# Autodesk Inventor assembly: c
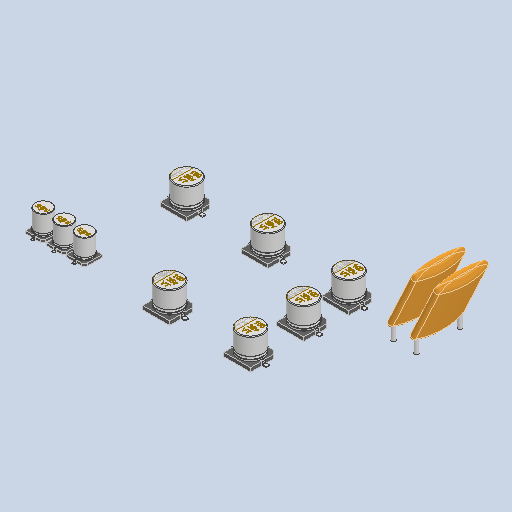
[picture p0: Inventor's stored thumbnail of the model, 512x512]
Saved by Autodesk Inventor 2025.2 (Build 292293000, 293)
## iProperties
Created: 2025-04
Part Number: c
Description: PART--DESC
Document SubType Name: Assembly
Designer: BennF
Author: BennF
Revision Number: NONE
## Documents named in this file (12)
- C:\Users\BennF\Nextcloud\Benutzer\CNC JarBeRi\existing parts\Electronics\RepRap A4988 Shied (USE WITHOUT ARDUINO)\reprap-a4988-1.snapshot.1\RepRap\RepRap\c.iam
- C:\Users\BennF\Nextcloud\Benutzer\CNC JarBeRi\existing parts\Electronics\RepRap A4988 Shied (USE WITHOUT ARDUINO)\reprap-a4988-1.snapshot.1\RepRap\RepRap\C100.iam
- C:\Users\BennF\Nextcloud\Benutzer\CNC JarBeRi\existing parts\Electronics\RepRap A4988 Shied (USE WITHOUT ARDUINO)\reprap-a4988-1.snapshot.1\RepRap\RepRap\C100_1.iam
- C:\Users\BennF\Nextcloud\Benutzer\CNC JarBeRi\existing parts\Electronics\RepRap A4988 Shied (USE WITHOUT ARDUINO)\reprap-a4988-1.snapshot.1\RepRap\RepRap\C100_2.iam
- C:\Users\BennF\Nextcloud\Benutzer\CNC JarBeRi\existing parts\Electronics\RepRap A4988 Shied (USE WITHOUT ARDUINO)\reprap-a4988-1.snapshot.1\RepRap\RepRap\C100_3.iam
- C:\Users\BennF\Nextcloud\Benutzer\CNC JarBeRi\existing parts\Electronics\RepRap A4988 Shied (USE WITHOUT ARDUINO)\reprap-a4988-1.snapshot.1\RepRap\RepRap\C100_4.iam
- C:\Users\BennF\Nextcloud\Benutzer\CNC JarBeRi\existing parts\Electronics\RepRap A4988 Shied (USE WITHOUT ARDUINO)\reprap-a4988-1.snapshot.1\RepRap\RepRap\C100_5.iam
- C:\Users\BennF\Nextcloud\Benutzer\CNC JarBeRi\existing parts\Electronics\RepRap A4988 Shied (USE WITHOUT ARDUINO)\reprap-a4988-1.snapshot.1\RepRap\RepRap\C10.iam
- C:\Users\BennF\Nextcloud\Benutzer\CNC JarBeRi\existing parts\Electronics\RepRap A4988 Shied (USE WITHOUT ARDUINO)\reprap-a4988-1.snapshot.1\RepRap\RepRap\C10_1.iam
- C:\Users\BennF\Nextcloud\Benutzer\CNC JarBeRi\existing parts\Electronics\RepRap A4988 Shied (USE WITHOUT ARDUINO)\reprap-a4988-1.snapshot.1\RepRap\RepRap\C10_2.iam
- C:\Users\BennF\Nextcloud\Benutzer\CNC JarBeRi\existing parts\Electronics\RepRap A4988 Shied (USE WITHOUT ARDUINO)\reprap-a4988-1.snapshot.1\RepRap\RepRap\Cp.iam
- C:\Users\BennF\Nextcloud\Benutzer\CNC JarBeRi\existing parts\Electronics\RepRap A4988 Shied (USE WITHOUT ARDUINO)\reprap-a4988-1.snapshot.1\RepRap\RepRap\Cp_1.iam
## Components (11 placed, 3 different names)
1. C100 [sub-assembly]
2. C100:1 [sub-assembly]
3. C100:2 [sub-assembly]
4. C100:3 [sub-assembly]
5. C100:4 [sub-assembly]
6. C100:5 [sub-assembly]
7. C10 [sub-assembly]
8. C10:1 [sub-assembly]
9. C10:2 [sub-assembly]
10. Cp [sub-assembly]
11. Cp:1 [sub-assembly]
